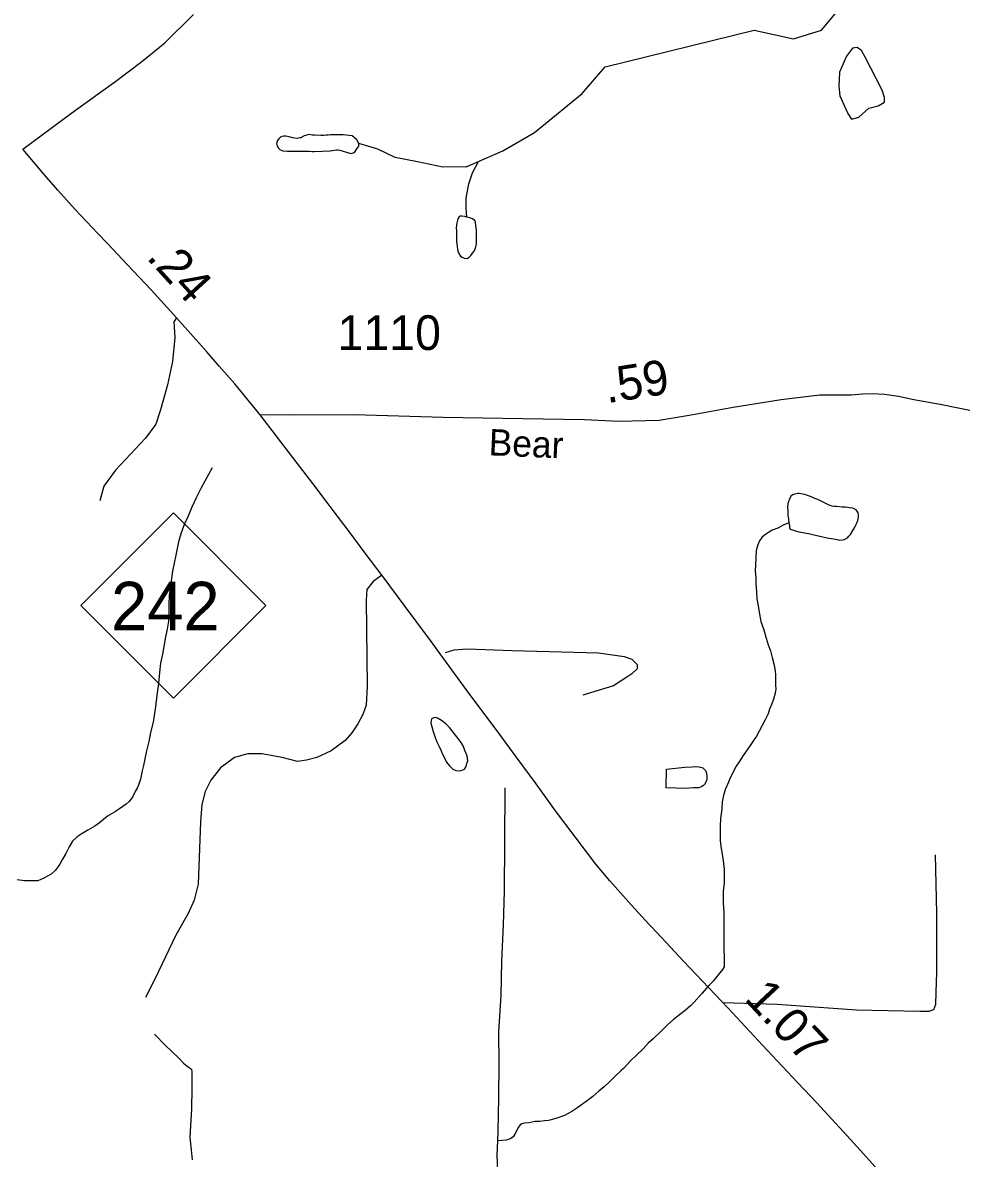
# Model space of a CAD drawing. Extents: x 2082433 to 2279600, y 546599 to 755198.
# Drawn here: x 2145947 to 2149322, y 565281 to 569366 of the extents above; entities that cross this region are included whole.
import ezdxf

# ---------------------------------------------------------------- set-up
doc = ezdxf.new("R2010")
doc.units = 0
for name, color, linetype in [('Exist Hydrographic Creek Single Shore', 7, 'Continuous'), ('Exist Hydrographic Misc Water Feature', 7, 'Continuous'), ('Exist Hydrographic Pond Under 1500 Sq Ft', 7, 'Continuous'), ('Exist Road Non-System Type 51', 7, 'Continuous'), ('Exist Road Primary NC Attributed', 7, 'Continuous'), ('Exist Road Primary NC Service Mileage Hundredths English Label', 7, 'Continuous'), ('Exist Road Primary NC Shield CELL', 7, 'Continuous'), ('Exist Road Primary NC Shield Number Label', 7, 'Continuous'), ('Exist Road Secondary Mileage Hundredths English Label', 7, 'Continuous'), ('Exist Road Secondary Type 51 Attributed', 7, 'Continuous'), ('Exist Road Secondary Type 51 Label', 7, 'Continuous'), ('Exist Road Secondary Type 51 Number Label', 7, 'Continuous')]:
    doc.layers.add(name, color=color, linetype=linetype)

msp = doc.modelspace()

# ---------------------------------------------------------------- linework, layer by layer
at = {"layer": 'Exist Hydrographic Creek Single Shore'}
for points in [[(2147541.4, 568847.3), (2147673.2, 568904.3), (2147787.4, 568970.2), (2147958.7, 569110.6), (2148042.2, 569207.2), (2148578, 569338.8), (2148718.6, 569308.1), (2148819.6, 569338.8), (2148971.9, 569522.5), (2149078.9, 569697.4), (2149161, 570013.9), (2149151.9, 570181.4), (2148950, 570615.2), (2148907.9, 570822.7), (2148905.9, 571255.8), (2148961.9, 571615.5), (2149118.9, 572015.8), (2149224.9, 572522.1)], [(2147541.4, 568847.3), (2147458, 568846.2), (2147366.8, 568865.2), (2147287, 568880.4), (2147224.3, 568910.8), (2147156.3, 568930.6)], [(2147544.5, 568666), (2147541.6, 568698.2), (2147541.6, 568734.2), (2147551.1, 568785.5), (2147564.4, 568825.4), (2147586.3, 568866.7)], [(2146628.3, 567764.8), (2146588.8, 567692.5), (2146570.7, 567656.8), (2146554.9, 567622.6), (2146541.2, 567588.2), (2146529.1, 567562.5), (2146517, 567530.2), (2146507.4, 567498.4), (2146497.3, 567450.5), (2146485.8, 567392.2), (2146479.9, 567348.5), (2146474.1, 567306.4), (2146472.3, 567272.2), (2146472.3, 567244.2), (2146470.9, 567212.4), (2146466.5, 567184.3), (2146460.6, 567156.3), (2146455.1, 567122.3), (2146449.5, 567094.3), (2146443.2, 567062.1), (2146439.3, 567028.2), (2146435.6, 566988.2), (2146429.8, 566946.1), (2146424.1, 566904.4), (2146416.3, 566850), (2146406.3, 566812.1), (2146400.5, 566780.2), (2146392.7, 566746.1), (2146386.8, 566718.2), (2146381, 566693.9), (2146376.9, 566673.9), (2146371, 566644), (2146365, 566626.2), (2146359.3, 566612), (2146351.3, 566599.9), (2146341.7, 566579.8), (2146329.6, 566563.8), (2146319.5, 566554), (2146307.4, 566545.7), (2146291.8, 566535.9), (2146277.7, 566525.8), (2146252.1, 566511.5), (2146223.8, 566487.3), (2146206.1, 566475.5), (2146181.9, 566461.3), (2146157.9, 566447), (2146142.4, 566437.2), (2146126.4, 566421), (2146114.1, 566400.9), (2146102.4, 566376.7), (2146090.7, 566357), (2146080.4, 566338.7), (2146064.9, 566316.7), (2146048.9, 566302.9), (2146022.8, 566288.6), (2146001.1, 566278.5), (2145975.2, 566278.4), (2145953.1, 566278.5), (2145926.9, 566282.4)]]:
    msp.add_lwpolyline(points, dxfattribs=at)
at = {"layer": 'Exist Hydrographic Misc Water Feature'}
for points in [[(2148702.2, 567566), (2148682.1, 567557.7), (2148662.7, 567547.7), (2148642.8, 567539.7), (2148628.6, 567531.7), (2148614.7, 567521.7), (2148604.6, 567513.4), (2148596.8, 567501.7), (2148591.1, 567487.5), (2148588.8, 567479.3)], [(2148588.8, 567479.3), (2148584.7, 567467.4), (2148583.1, 567439.2), (2148580.8, 567393.4), (2148583.3, 567367.4), (2148583.5, 567347.5), (2148585.6, 567319.6), (2148587.6, 567293.4), (2148591.9, 567267.6), (2148595.8, 567245.5), (2148601.6, 567211.8), (2148612, 567181.9), (2148620.6, 567151.8), (2148628.4, 567127.8), (2148636.2, 567106), (2148642.6, 567081.9), (2148648.5, 567059.9), (2148652.8, 567033.8), (2148654.7, 567020.1), (2148654.7, 566999.8), (2148654.7, 566981.9), (2148655.3, 566969.7), (2148653, 566953.8), (2148647.3, 566932), (2148641.1, 566915.9), (2148633.1, 566896), (2148627.6, 566879.8), (2148615.5, 566855.7), (2148605.7, 566837.7), (2148595.4, 566817.7), (2148585.8, 566799.7), (2148577.8, 566787.6), (2148565.9, 566769.5), (2148552.3, 566749.7), (2148537.8, 566729.5), (2148524, 566707.3), (2148512.4, 566691.2), (2148490.6, 566649.5), (2148484.9, 566633.3), (2148474.4, 566609.3), (2148467, 566587.4), (2148462.5, 566563.3), (2148461.1, 566537.2), (2148459, 566519.2), (2148456.8, 566503.3), (2148455.3, 566477.2), (2148455.1, 566445.2), (2148455.3, 566423.3), (2148457.6, 566403.5), (2148466, 566351.5), (2148469.9, 566319.3), (2148470.1, 566271.4), (2148466.4, 566241.5), (2148466.4, 566229.4), (2148466.4, 566199.3), (2148468.5, 566165.4), (2148468.5, 566139.4), (2148468.7, 566115.5), (2148468.9, 566091.5), (2148468.9, 566063.6), (2148468.9, 566035.6), (2148469.1, 566003.5), (2148469.5, 565977.5), (2148469.5, 565969.4), (2148463.6, 565959.3), (2148449.4, 565941.6), (2148429.7, 565917.4), (2148416, 565903.3), (2148389.7, 565873.2), (2148362.1, 565842.9), (2148348.3, 565829.1), (2148329.9, 565812.9), (2148304.4, 565792.8), (2148286.4, 565778.9), (2148266.3, 565760.8), (2148242.7, 565738.4), (2148214.6, 565710.7), (2148196.6, 565694.3), (2148178.7, 565674.3), (2148154.7, 565652), (2148131, 565630), (2148107.2, 565604), (2148099.4, 565595.9), (2148077.4, 565575.7), (2148057.3, 565555.6), (2148037.5, 565537.9), (2148019.4, 565521.6), (2147997.3, 565503.5), (2147973.9, 565485.5), (2147943.9, 565463.3), (2147922, 565449.1), (2147895.8, 565435.2), (2147868.1, 565424.8), (2147848, 565419), (2147837.9, 565416.8), (2147824, 565414.9), (2147806.2, 565412.7), (2147790.2, 565412.7), (2147768.2, 565408.7), (2147752, 565406.7)], [(2147681.4, 566613), (2147679.8, 566417.6), (2147678.6, 566241.8), (2147674.9, 566119.9), (2147669.4, 565989.8), (2147666.3, 565866.1), (2147658.5, 565735.9), (2147659.1, 565621.9), (2147658.1, 565498), (2147656.3, 565378.2), (2147654.4, 565344)], [(2146421.4, 565726.7), (2146461, 565686.7), (2146481.5, 565666.9), (2146509.6, 565639.1), (2146525.6, 565622.9), (2146543.2, 565609), (2146553.9, 565601.3), (2146555.5, 565591.3), (2146555.5, 565565.3), (2146555.7, 565531.2), (2146554.5, 565459.2), (2146550.6, 565397.4), (2146548.6, 565355.5), (2146553.3, 565311.4), (2146557, 565275.1)], [(2147752, 565406.7), (2147742, 565404.6), (2147736.2, 565400.6), (2147730.1, 565392.6), (2147718.4, 565370.4), (2147710.4, 565358.2), (2147702.2, 565352.2), (2147694.4, 565348.5), (2147686.2, 565346.1), (2147654.4, 565344)], [(2147654.4, 565344), (2147652.6, 565291.9), (2147655.2, 565208), (2147659.5, 565170.1), (2147667.3, 565132.4), (2147675.3, 565104.4), (2147691.7, 565072.3), (2147707.7, 565036.2), (2147716.1, 565020.9)]]:
    msp.add_lwpolyline(points, dxfattribs=at)
at = {"layer": 'Exist Hydrographic Pond Under 1500 Sq Ft'}
for points in [[(2148976.8, 569241.9), (2148964, 569265.1), (2148947.4, 569276.5), (2148930.7, 569274.5), (2148909.9, 569245.4), (2148884.3, 569187.4), (2148881.9, 569137.4), (2148886, 569102), (2148914, 569038.8), (2148927.6, 569019), (2148953.6, 569026.2), (2148990, 569058.4), (2149023.2, 569066.7), (2149046.1, 569080.2), (2149046.1, 569096.9), (2149037.9, 569123), (2148976.8, 569241.9)], [(2147080.1, 568908.2), (2147087.3, 568906.9), (2147127.6, 568894.6), (2147139.9, 568898.7), (2147148.1, 568912.3), (2147156.3, 568921.9), (2147156.3, 568931.4), (2147148.1, 568944.4), (2147131.7, 568958.7), (2147099.6, 568962.1), (2147066.8, 568962.8), (2147053.8, 568962.8), (2147045, 568960.8), (2147038.1, 568960.8), (2147028.6, 568960.1), (2147019.7, 568960.1), (2146997.2, 568961.5), (2146987.6, 568961.5), (2146976.7, 568963.5), (2146964.4, 568960.1), (2146958.8, 568958.3), (2146952.3, 568954.9), (2146948.8, 568951.9), (2146944.2, 568951.2), (2146933.5, 568949.5), (2146917.7, 568951.5), (2146905.6, 568955.3), (2146893.7, 568957.5), (2146885.5, 568957.5), (2146875.9, 568955.4), (2146869.7, 568949.4), (2146861.9, 568941.2), (2146860.1, 568929.3), (2146861.9, 568923.4), (2146866.3, 568915.4), (2146872, 568909.3), (2146882, 568905.3), (2146898.2, 568903.3), (2146914, 568903.3), (2146930.2, 568903.7), (2146945.8, 568903.8), (2146960, 568903.7), (2146968, 568903.7), (2146978.2, 568903.8), (2146988.1, 568901.9), (2146995.1, 568902.1), (2147053.2, 568904.8), (2147075.7, 568908.2), (2147080.1, 568908.2)], [(2147526.6, 568669.9), (2147520.7, 568670), (2147516.4, 568667.8), (2147514.5, 568663.6), (2147510.6, 568655.7), (2147508.6, 568645.9), (2147506.3, 568628), (2147506.5, 568615.8), (2147507.2, 568593.8), (2147507, 568578), (2147509, 568561.9), (2147510.8, 568549.8), (2147513.3, 568541.7), (2147515.2, 568535.8), (2147521.3, 568526), (2147527, 568521.9), (2147535.2, 568518.2), (2147545.1, 568517.9), (2147552.9, 568522), (2147559, 568528), (2147565.2, 568536.4), (2147571.1, 568543.9), (2147574.8, 568554.4), (2147578.7, 568570), (2147578.9, 568584.1), (2147578.9, 568594.3), (2147578.9, 568606.1), (2147578.5, 568622.3), (2147576.7, 568634.4), (2147574.8, 568648), (2147572.4, 568654.1), (2147564.4, 568660.1), (2147554.5, 568664.1), (2147544.7, 568666), (2147536.5, 568668), (2147526.6, 568669.9)], [(2148702.2, 567566), (2148704.5, 567556), (2148704.3, 567549.9), (2148706.7, 567543.9), (2148738.7, 567534.1), (2148772.6, 567528.2), (2148782.4, 567526.3), (2148840.4, 567512.7), (2148862.4, 567508.6), (2148876.5, 567506.8), (2148884.7, 567504.8), (2148894.6, 567504.9), (2148902.6, 567507), (2148912.8, 567512.7), (2148918.4, 567518.7), (2148924.5, 567524.7), (2148932.5, 567538.9), (2148940.3, 567553.2), (2148944.2, 567561), (2148950.3, 567575.1), (2148952.4, 567587), (2148952.4, 567597.1), (2148952, 567602.9), (2148947.9, 567609.1), (2148944.4, 567612.9), (2148932.1, 567618.9), (2148920.2, 567620.7), (2148906.1, 567622.8), (2148894.2, 567622.6), (2148874.1, 567624.8), (2148866.1, 567624.8), (2148858.3, 567626.8), (2148847.8, 567630.4), (2148830, 567638.4), (2148818.3, 567644.2), (2148806, 567650.5), (2148796.1, 567654.4), (2148785.7, 567658.4), (2148759.6, 567668), (2148752.1, 567670), (2148739.6, 567672.3), (2148734, 567671.9), (2148724, 567670.2), (2148716, 567667.8), (2148710, 567663.8), (2148706.3, 567655.8), (2148702, 567645.9), (2148698.3, 567635.9), (2148697.9, 567621.8), (2148698.3, 567608), (2148698.5, 567593.8), (2148700.4, 567580.1), (2148702.2, 567566)], [(2147535.9, 566680.1), (2147541.9, 566690.2), (2147543.9, 566700.4), (2147547.8, 566710.4), (2147545.6, 566728.1), (2147537.4, 566748), (2147531.8, 566762.2), (2147523.4, 566776.1), (2147511.7, 566792), (2147495.3, 566814), (2147481.4, 566829.9), (2147469.3, 566843.9), (2147453.3, 566855.6), (2147439.3, 566863.8), (2147431.3, 566865.9), (2147425.2, 566865.5), (2147417.4, 566861.4), (2147415.6, 566855.6), (2147415.1, 566845.6), (2147417.2, 566837.6), (2147419.3, 566829.6), (2147423.4, 566815.6), (2147429.7, 566797.6), (2147435.5, 566781.7), (2147443.7, 566763.8), (2147451.6, 566745.9), (2147457.8, 566731.6), (2147465.8, 566715.9), (2147471.7, 566706), (2147482.2, 566691.9), (2147494.3, 566679.9), (2147504.1, 566676), (2147514, 566674.1), (2147524.2, 566676.2), (2147535.9, 566680.1)], [(2148328.6, 566687.1), (2148354.9, 566689.3), (2148366.8, 566689.5), (2148378.7, 566689.3), (2148384.8, 566687.6), (2148392.4, 566685.6), (2148396.5, 566681.8), (2148402.7, 566675.6), (2148406.5, 566665.6), (2148406.8, 566653.5), (2148406.8, 566643.7), (2148403.1, 566633.7), (2148398.5, 566625.5), (2148395.1, 566621.6), (2148388.9, 566617.6), (2148378.9, 566613.5), (2148358.8, 566613.3), (2148330.9, 566611.4), (2148261.4, 566613), (2148262.4, 566680.9), (2148328.6, 566687.1)]]:
    msp.add_lwpolyline(points, dxfattribs=at)
at = {"layer": 'Exist Road Non-System Type 51'}
for points in [[(2146500.6, 568304.2), (2146491.1, 568290), (2146494.7, 568233.2), (2146485.8, 568146.4), (2146468.1, 568063), (2146443.2, 567972.6), (2146425.5, 567921.2), (2146388.3, 567871.6), (2146281, 567755.5), (2146238.5, 567698.7), (2146224.3, 567645.5)], [(2147238.2, 567378.5), (2147207.3, 567355.7), (2147184.3, 567327.3), (2147182.5, 567288.3), (2147186.1, 566978.1), (2147182.5, 566910.7), (2147170.1, 566877), (2147152.4, 566843.3), (2147131.1, 566811.4), (2147106.3, 566783.1), (2147055.8, 566746.7), (2147004.3, 566721.9), (2146967.1, 566713), (2146935.2, 566707.7), (2146880.2, 566721.9), (2146807.6, 566736.1), (2146756.1, 566736.1), (2146708.3, 566721.9), (2146658.6, 566684.7), (2146623.2, 566640.3), (2146603.7, 566599.6), (2146591.3, 566553.5), (2146586, 566491.4), (2146578, 566267.2), (2146563.8, 566208.7), (2146542.5, 566160.8), (2146498.2, 566082.8), (2146422.9, 565927.7), (2146389.2, 565858.5)], [(2147467.9, 567100.4), (2147498.1, 567109.3), (2147545.9, 567112.8), (2147707.3, 567107.5), (2148017.5, 567098.6), (2148110.6, 567085.3), (2148137.2, 567076.5), (2148156.7, 567057), (2148156.7, 567041), (2148137.2, 567023.3), (2148119.4, 567010.9), (2148071.6, 566980.7), (2147961.7, 566947)], [(2148464.2, 565841.5), (2148659.7, 565835), (2148945.2, 565814.6), (2149172.9, 565809.5), (2149206.9, 565809.5), (2149223.9, 565816.3), (2149230.7, 565835), (2149232.4, 565877.5), (2149234.1, 565950.6), (2149234.1, 566163), (2149229.8, 566372)]]:
    msp.add_lwpolyline(points, dxfattribs=at)
at = {"layer": 'Exist Road Primary NC Attributed'}
for points in [[(2146800.6, 567955.4), (2146709.4, 568066), (2146654.1, 568130.7), (2146609.4, 568182.1), (2146501.4, 568303.3), (2146408.9, 568404.9), (2146323, 568495.9), (2146251.6, 568571.9), (2146217.5, 568607.2), (2146136.2, 568693.4), (2146073.4, 568762.9), (2146024.8, 568819), (2145947.1, 568911.3)], [(2149051.9, 565205.4), (2148982, 565284.4), (2148924.5, 565348.3), (2148802.9, 565479.7), (2148732.9, 565553.8), (2148607.7, 565687.3), (2148483.1, 565821.6), (2148322.9, 565990.1), (2148244.2, 566075.1), (2148186, 566137.1), (2148136.6, 566190.7), (2148058.8, 566278.3), (2148008.3, 566338.9), (2147933.9, 566436.7), (2147863.6, 566530.3), (2147793.3, 566627.3), (2147722.1, 566724.9), (2147649.2, 566823.4), (2147555.5, 566949.4), (2147458.1, 567082.7), (2147413, 567143.4), (2147318.9, 567270.2), (2147242.9, 567372.3), (2147175.6, 567462.1), (2147120.6, 567535.4), (2147063.4, 567611.5), (2147042, 567639.2), (2146990.4, 567708.1), (2146919, 567802.1), (2146800.6, 567955.4)]]:
    msp.add_lwpolyline(points, dxfattribs=at)
at = {"layer": 'Exist Road Primary NC Shield CELL'}
msp.add_lwpolyline([(2146155.8, 567269.2), (2146488.8, 567602.2), (2146821.8, 567269.2), (2146488.8, 566936.2)], close=True, dxfattribs=at)
at = {"layer": 'Exist Road Secondary Type 51 Attributed'}
for points in [[(2145947.1, 568911.3), (2146123.4, 569041.3), (2146217.9, 569110), (2146282.3, 569155.2), (2146375.1, 569225.7), (2146458.3, 569293.8), (2146561.7, 569394.7)], [(2149382.4, 567964.1), (2149245.8, 567991.8), (2149152, 568009.5), (2149096.2, 568020.7), (2149046.3, 568027.7), (2149002.4, 568030.5), (2148968.4, 568029.2), (2148926.3, 568026.1), (2148814, 568026.3), (2148674.9, 568009.6), (2148502.3, 567981.8), (2148344.2, 567952.1), (2148236.4, 567935.2), (2148090.3, 567931.6), (2147967.8, 567937.2), (2147744.3, 567940.3), (2147459.2, 567945.3), (2147139.1, 567955.3), (2146924.7, 567953.5), (2146800.6, 567955.4)]]:
    msp.add_lwpolyline(points, dxfattribs=at)

# ---------------------------------------------------------------- texts
at = {"layer": 'Exist Road Primary NC Service Mileage Hundredths English Label'}
for s, rotation, p in [('.24', 312.3297, (2146389.1, 568519.3)), ('1.07', 313.1747, (2148538.7, 565852.1))]:
    msp.add_text(s, height=125, rotation=rotation, dxfattribs=at).set_placement(p)
at = {"layer": 'Exist Road Primary NC Shield Number Label'}
msp.add_text('242', height=175, dxfattribs=at).set_placement((2146264.9, 567179.5))
at = {"layer": 'Exist Road Secondary Mileage Hundredths English Label'}
msp.add_text('.59', height=125, rotation=8.8857, dxfattribs=at).set_placement((2148048.1, 567996.7))
at = {"layer": 'Exist Road Secondary Type 51 Label'}
msp.add_text('Bear', height=95, rotation=357.5529, dxfattribs=at).set_placement((2147621.4, 567809.6))
at = {"layer": 'Exist Road Secondary Type 51 Number Label'}
msp.add_text('1110', height=125, dxfattribs=at).set_placement((2147079.3, 568188.2))

doc.saveas('drawing.dxf')
